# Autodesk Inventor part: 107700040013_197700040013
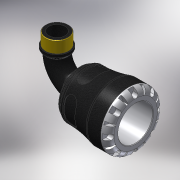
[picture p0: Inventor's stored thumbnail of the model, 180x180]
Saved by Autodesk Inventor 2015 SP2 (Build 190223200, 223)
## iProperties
Created: 2016-12
Part Number: 107700040013_197700040013
Material: PVC-Piping
Description: PLASSON 90° ELBOW WITH MALE INTEGRAL BRASS 40X1.1/4" SERIES 1
Document SubType Name: Modeling
Designer: KIM
Mass: 664.223 g
Surface Area: 733.008 cm^2
Volume: 474.445 cm^3
Density: 1.4 g/cm^3
Appearance: Black Cast
Author: KIM
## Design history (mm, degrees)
derived "1077.ipt"
feature "Solid1::1077.ipt"
tag "TaggingFeature1"
body "Solid1"
other parameters: "d1" = 29.82, "d8" = 59.5, "d13" = 8, "d14" = 8, "d15" = 0, "d17" = 360 deg, "d19" = 8 deg, "d20" = 0.8, "d21" = 0.8, "d22" = 8 deg, "d24" = 0, "d26" = 360 deg, "d33" = 7, "d43" = 54.6, "d51" = 0.7, "d54" = 14, "d55" = 8.8, "d57" = 15.68, "d58" = 0, "d74" = 0, "d78" = 71, "d82" = 0.8, "d115" = 360 deg, "d207" = 90 deg, "d228" = 11.9, "d247" = 1.4, "d248" = 4.26, "d268" = 32.725, "d269" = 4.26, "d270" = 104, "d276" = 41.91, "d277" = 21, "d278" = 46.101, "d279" = 68, "d280" = 27.3, "d281" = 6.2865, "d283" = 37.719, "d286" = 0, "d287" = 0, "d288" = 29.337, "d290" = 8.4405, "d292" = 30 deg, "d294" = 4.191, "d296" = 30 deg, "l_" = 71, "A_" = 104, "A_1" = 68, "l_2" = 21, "R_" = 41.91, "d289" = 29.337
